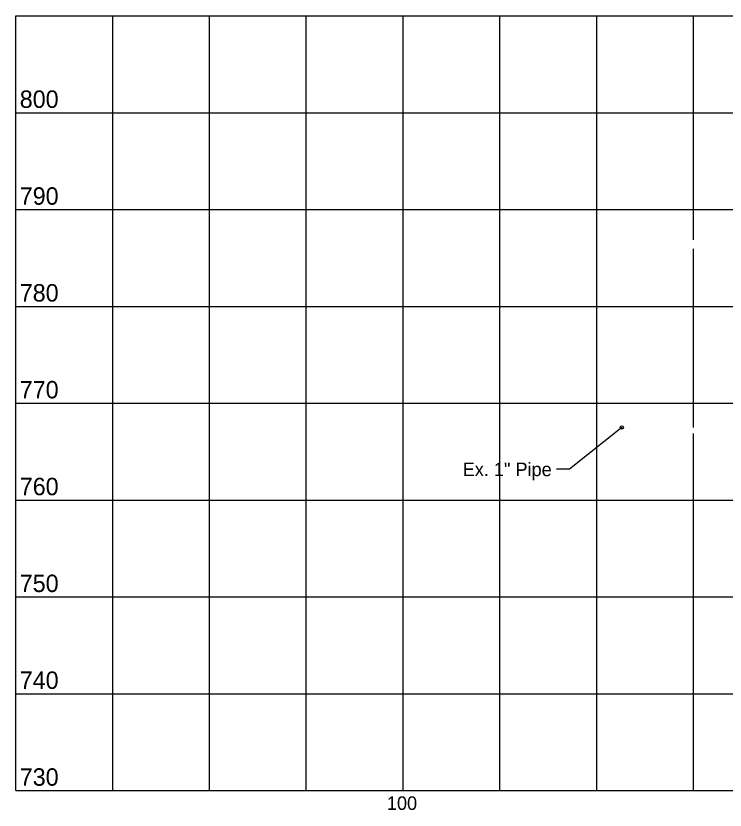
# Model space of a CAD drawing. Extents: x -1395 to 1843, y -1176 to 1887.
# Drawn here: x -1180.1 to -1033.6, y 1723.4 to 1887.4 of the extents above; entities that cross this region are included whole.
import ezdxf

# ---------------------------------------------------------------- set-up
doc = ezdxf.new("R2010")
doc.units = 0
for name, color, linetype in [('GE_X_Alignment', 7, 'Continuous'), ('RW_P_Esmt_TMP', 7, 'Continuous'), ('SH_Data', 7, 'Continuous'), ('SV_X_Break_Lines', 7, 'Continuous'), ('SV_X_Shot_Marker', 7, 'Continuous')]:
    doc.layers.add(name, color=color, linetype=linetype)

msp = doc.modelspace()

# ---------------------------------------------------------------- linework, layer by layer
at = {"layer": 'GE_X_Alignment'}
for p, q in [((-1180.15, 1887.4), (-620.15, 1887.4)), ((-1054.96, 1802.4), (-1065.8, 1793.78)), ((-1065.8, 1793.78), (-1068.48, 1793.78))]:
    msp.add_line(p, q, dxfattribs=at)
at = {"layer": 'RW_P_Esmt_TMP'}
for p, q in [((-1180.15, 1727.4), (-1180.15, 1887.4)), ((-1160.15, 1727.4), (-1160.15, 1887.4)), ((-1140.15, 1727.4), (-1140.15, 1887.4)), ((-1120.15, 1727.4), (-1120.15, 1887.4)), ((-1100.15, 1727.4), (-1100.15, 1887.4)), ((-1080.15, 1727.4), (-1080.15, 1887.4)), ((-1060.15, 1727.4), (-1060.15, 1887.4)), ((-1040.15, 1841.16), (-1040.15, 1887.4)), ((-1180.15, 1867.4), (-620.15, 1867.4)), ((-1180.15, 1847.4), (-620.15, 1847.4)), ((-1180.15, 1827.4), (-620.15, 1827.4)), ((-1180.15, 1807.4), (-620.15, 1807.4)), ((-1040.15, 1727.4), (-1040.15, 1801.16)), ((-1180.15, 1787.4), (-620.15, 1787.4)), ((-1180.15, 1767.4), (-620.15, 1767.4)), ((-1180.15, 1747.4), (-620.15, 1747.4)), ((-1180.15, 1727.4), (-620.15, 1727.4))]:
    msp.add_line(p, q, dxfattribs=at)
at = {"layer": 'SV_X_Break_Lines'}
msp.add_line((-1040.15, 1802.37), (-1040.15, 1839.28), dxfattribs=at)
at = {"layer": 'SV_X_Shot_Marker'}
msp.add_circle((-1054.96, 1802.4), 0.333, dxfattribs=at)

# ---------------------------------------------------------------- texts
at = {"layer": 'SH_Data'}
for s, height, p in [('800', 3.6, (-1179.35, 1868.4)), ('790', 3.6, (-1179.35, 1848.4)), ('780', 3.6, (-1179.35, 1828.4)), ('770', 3.6, (-1179.35, 1808.4)), ('Ex. 1" Pipe', 2.8, (-1087.84, 1792.34)), ('760', 3.6, (-1179.35, 1788.4)), ('750', 3.6, (-1179.35, 1768.4)), ('740', 3.6, (-1179.35, 1748.4)), ('730', 3.6, (-1179.35, 1728.4)), ('100', 2.8, (-1103.5, 1723.4))]:
    msp.add_text(s, height=height, dxfattribs=at).set_placement(p)

doc.saveas('drawing.dxf')
